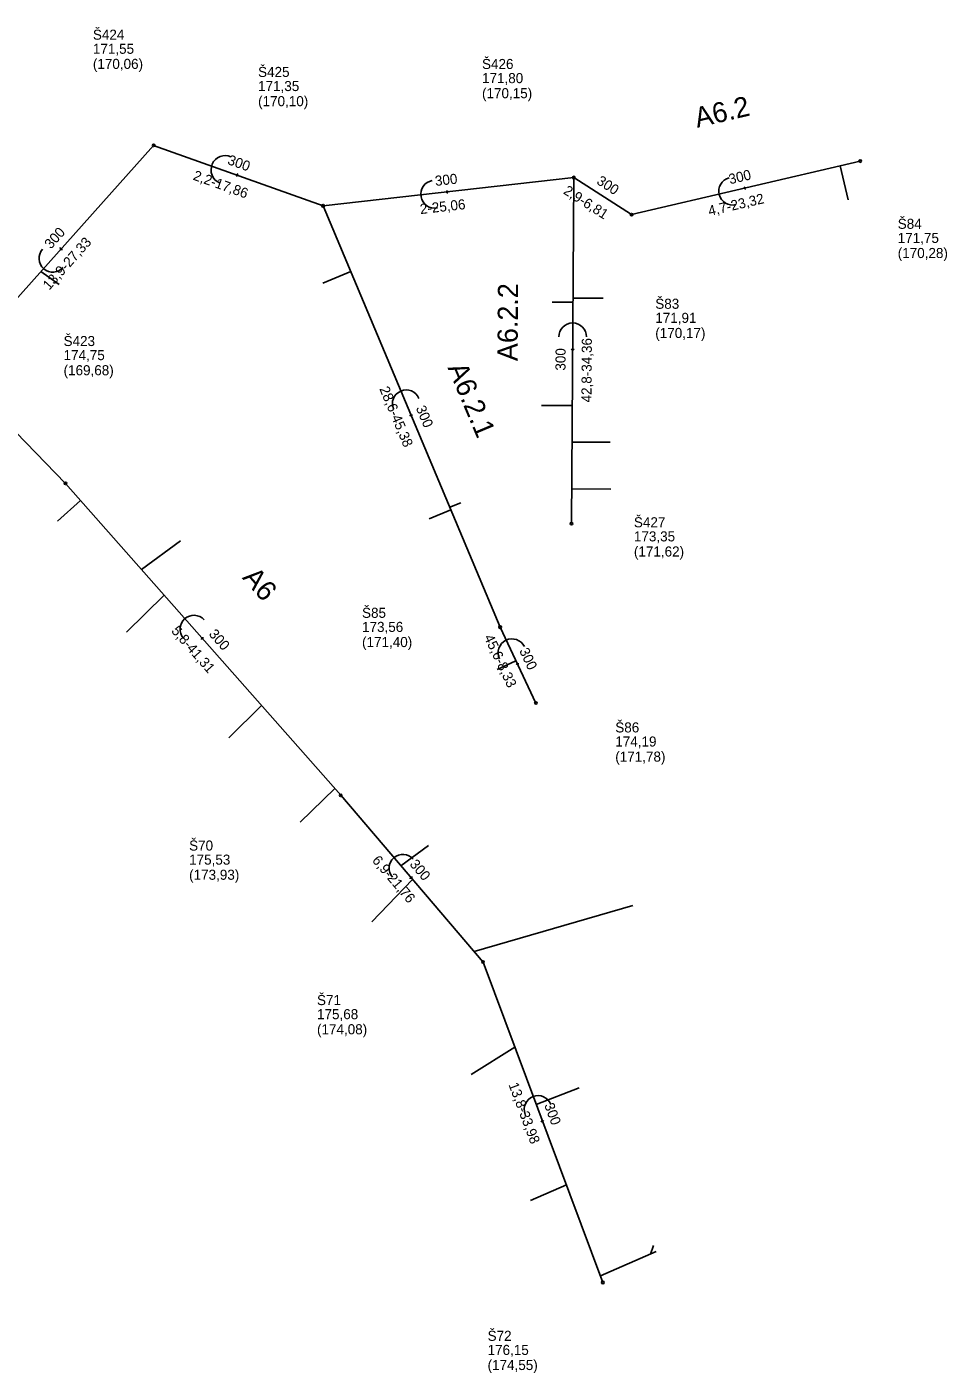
# Model space of a CAD drawing. Extents: x -548529 to -543591, y -1201432 to -1192608.
# Drawn here: x -546811.8 to -546720.5, y -1194923.8 to -1194790.1 of the extents above; entities that cross this region are included whole.
import ezdxf

# ---------------------------------------------------------------- set-up
doc = ezdxf.new("R2010")
doc.units = 0
for name, color, linetype in [('C3D_Bod-Značky', 7, 'Continuous'), ('C3D_Koridor', 7, 'Continuous'), ('C3D_Křižovatka', 7, 'Continuous'), ('C3D_Netisknutelná', 7, 'Continuous'), ('C3D_PP-zobrazeni v PR', 7, 'Continuous'), ('C3D_PR-Popisek', 7, 'Continuous'), ('C3D_SPR-Popisek', 7, 'Continuous'), ('C3D_Tlakove_potrubi_Popis', 7, 'Continuous'), ('C3D_ZPR-Formaty', 7, 'Continuous')]:
    doc.layers.add(name, color=color, linetype=linetype)

# ---------------------------------------------------------------- blocks, each defined once
blk = doc.blocks.new('100')
at = {"layer": 'Defpoints'}
blk.add_circle((0, 0), 0.127, dxfattribs=at)
blk = doc.blocks.new('86')
at = {"layer": 'Defpoints'}
blk.add_lwpolyline([(0.08, 0.14), (0.19, 0), (0.08, -0.14)], dxfattribs=at)
blk.add_arc((1.37, 0), 1.37, 270, 90, dxfattribs=at)
blk = doc.blocks.new('91')
at = {"layer": 'Defpoints'}
blk.add_lwpolyline([(0.08, 0.14), (0.19, 0), (0.08, -0.14)], dxfattribs=at)
blk.add_arc((1.37, 0), 1.37, 270, 90, dxfattribs=at)

msp = doc.modelspace()

# ---------------------------------------------------------------- linework, layer by layer
at = {"layer": 'C3D_Bod-Značky'}
for points in [[(-546799.24, -1194801.84), (-546817.46, -1194822.21)], [(-546782.42, -1194807.84), (-546799.24, -1194801.84)], [(-546729.09, -1194803.4), (-546751.79, -1194808.72)], [(-546757.52, -1194805.04), (-546782.42, -1194807.84)], [(-546757.76, -1194839.4), (-546757.52, -1194805.04)], [(-546751.79, -1194808.72), (-546757.52, -1194805.04)], [(-546764.84, -1194849.68), (-546782.42, -1194807.84)], [(-546807.989, -1194835.403), (-546818.831, -1194824.231)], [(-546780.666, -1194866.381), (-546807.989, -1194835.403)], [(-546761.29, -1194857.22), (-546764.84, -1194849.68)], [(-546766.539, -1194882.936), (-546780.666, -1194866.381)], [(-546754.646, -1194914.766), (-546766.539, -1194882.936)]]:
    msp.add_lwpolyline(points, dxfattribs=at)
at = {"layer": 'C3D_Koridor'}
for points in [[(-546731.091, -1194803.869), (-546730.283, -1194807.266)], [(-546810.431, -1194814.352), (-546808.618, -1194815.672)], [(-546779.677, -1194814.367), (-546782.443, -1194815.529)], [(-546757.604, -1194817.01), (-546754.604, -1194817.031)], [(-546757.606, -1194817.42), (-546759.689, -1194817.405)], [(-546757.678, -1194827.679), (-546760.741, -1194827.659)], [(-546757.704, -1194831.319), (-546753.918, -1194831.326)], [(-546757.736, -1194835.949), (-546753.862, -1194835.984)], [(-546806.493, -1194837.099), (-546808.777, -1194839.173)], [(-546769.734, -1194838.033), (-546771.874, -1194838.932)], [(-546769.838, -1194837.784), (-546768.754, -1194837.329)], [(-546800.447, -1194843.953), (-546796.562, -1194841.101)], [(-546798.186, -1194846.518), (-546801.925, -1194850.167)], [(-546763.269, -1194853.019), (-546765.131, -1194853.895)], [(-546788.53, -1194857.465), (-546791.79, -1194860.667)], [(-546781.261, -1194865.707), (-546784.704, -1194869.043)], [(-546774.694, -1194873.38), (-546771.946, -1194871.361)], [(-546773.538, -1194874.735), (-546777.588, -1194878.96)], [(-546767.421, -1194881.903), (-546751.662, -1194877.321)], [(-546763.379, -1194891.394), (-546767.73, -1194894.113)], [(-546761.251, -1194897.09), (-546757.01, -1194895.42)], [(-546758.269, -1194905.071), (-546761.839, -1194906.608)], [(-546754.891, -1194914.11), (-546749.361, -1194911.7)], [(-546749.906, -1194911.937), (-546749.629, -1194911.086)]]:
    msp.add_lwpolyline(points, dxfattribs=at)

# ---------------------------------------------------------------- block references
at = {"layer": 'C3D_PP-zobrazeni v PR'}
for p, xscale, yscale, rotation in [((-546799.24, -1194801.84), 0.999999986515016, 0.9999999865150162, 15.000000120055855), ((-546729.09, -1194803.4), 1.0009848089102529, 1.000984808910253, 14.224326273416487), ((-546757.52, -1194805.04), 1.0028916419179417, 1.0028916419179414, -13.69720873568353), ((-546782.42, -1194807.84), 1.0011217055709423, 1.0011217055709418, -6.582609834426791), ((-546751.79, -1194808.72), 1.008377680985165, 1.0083776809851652, -11.626378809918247), ((-546807.989, -1194835.403), 1.00000000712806, 1.00000000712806, 133.00000056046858), ((-546764.84, -1194849.68), 0.9999999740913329, 0.9999999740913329, -65.99999939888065), ((-546761.29, -1194857.22), 1.0000000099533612, 1.0000000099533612, -63.999999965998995), ((-546780.666, -1194866.381), 1.0000000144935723, 1.0000000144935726, 130.99999910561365), ((-546766.539, -1194882.936), 1.0000000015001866, 1.0000000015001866, 120.99999982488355), ((-546754.646, -1194914.766), 0.9999999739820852, 0.9999999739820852, -68.99999941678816)]:
    msp.add_blockref('100', p, dxfattribs=dict(at, xscale=xscale, yscale=yscale, rotation=rotation))
at = {"layer": 'C3D_PP-zobrazeni v PR', "rotation": -90}
msp.add_blockref('100', (-546757.76, -1194839.4), dxfattribs=at)
at = {"layer": 'C3D_SPR-Popisek'}
for name, p, xscale, yscale, rotation in [('86', (-546790.83, -1194804.84), 1.0316957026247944, 1.0316957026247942, 156.4154111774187), ('86', (-546769.97, -1194806.44), 1.0098116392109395, 1.0098116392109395, -169.38969821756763), ('86', (-546740.44, -1194806.06), 1.0009848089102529, 1.000984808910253, -165.77567372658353), ('86', (-546808.35, -1194812.025), 1.0000000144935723, 1.0000000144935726, -130.99999910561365), ('86', (-546773.63, -1194828.76), 1.0000000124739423, 1.000000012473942, 112.99999954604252), ('91', (-546794.327, -1194850.892), 1.0000000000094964, 1.0000000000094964, 132.0000013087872), ('86', (-546763.065, -1194853.45), 1.0000000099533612, 1.0000000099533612, 116.000000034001), ('91', (-546773.602, -1194874.658), 1.0000000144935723, 1.0000000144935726, 130.99999910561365), ('91', (-546760.592, -1194898.851), 0.9999999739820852, 0.9999999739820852, 111.00000058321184)]:
    msp.add_blockref(name, p, dxfattribs=dict(at, xscale=xscale, yscale=yscale, rotation=rotation))
at = {"layer": 'C3D_SPR-Popisek', "rotation": 90}
msp.add_blockref('86', (-546757.64, -1194822.22), dxfattribs=at)

# ---------------------------------------------------------------- texts
at = {"layer": 'C3D_Křižovatka'}
for s, p in [('Š424', (-546805.27, -1194791.35)), ('Š426', (-546766.64, -1194794.26)), ('Š425', (-546788.87, -1194795.05)), ('Š84', (-546725.37, -1194810.13)), ('Š83', (-546749.44, -1194818.07)), ('Š423', (-546808.18, -1194821.77)), ('Š427', (-546751.56, -1194839.77)), ('Š85', (-546778.55, -1194848.76)), ('Š86', (-546753.41, -1194860.14)), ('Š70', (-546795.716, -1194871.871)), ('Š71', (-546783.019, -1194887.216)), ('Š72', (-546766.086, -1194920.556))]:
    msp.add_text(s, height=1, dxfattribs=at).set_placement(p)
at = {"layer": 'C3D_Netisknutelná'}
for s, rotation, p in [('A6.2', 13.19, (-546745.28, -1194800.107)), ('A6.2.2', 89.6, (-546763.112, -1194823.268)), ('A6.2.1', 292.79, (-546770.079, -1194823.915)), ('A6', 311.41, (-546790.497, -1194844.808))]:
    msp.add_text(s, height=2, rotation=rotation, dxfattribs=at).set_placement(p)
at = {"layer": 'C3D_PR-Popisek'}
for rotation, p in [(340.37, (-546791.977, -1194803.688)), (6.42, (-546771.255, -1194805.876)), (327.29, (-546755.341, -1194805.608)), (13.19, (-546742.021, -1194805.709)), (48.19, (-546809.437, -1194812.196)), (89.6, (-546758.354, -1194824.214)), (292.79, (-546773.227, -1194827.92)), (311.41, (-546793.822, -1194850.413)), (295.21, (-546762.967, -1194852.021)), (310.48, (-546773.882, -1194873.258)), (290.49, (-546760.48, -1194897.141))]:
    msp.add_text('300', height=1, rotation=rotation, dxfattribs=at).set_placement(p)
at = {"layer": 'C3D_Tlakove_potrubi_Popis'}
for s, p in [('171,55 ', (-546805.27, -1194792.75)), ('(170,06)', (-546805.27, -1194794.25)), ('171,35 ', (-546788.87, -1194796.45)), ('171,80 ', (-546766.64, -1194795.66)), ('(170,10)', (-546788.87, -1194797.95)), ('(170,15)', (-546766.64, -1194797.16)), ('171,75 ', (-546725.37, -1194811.53)), ('(170,28)', (-546725.37, -1194813.03)), ('171,91 ', (-546749.44, -1194819.47)), ('(170,17)', (-546749.44, -1194820.97)), ('174,75 ', (-546808.18, -1194823.17)), ('(169,68)', (-546808.18, -1194824.67)), ('173,35 ', (-546751.56, -1194841.17)), ('(171,62)', (-546751.56, -1194842.67)), ('173,56 ', (-546778.55, -1194850.16)), ('(171,40)', (-546778.55, -1194851.66)), ('174,19 ', (-546753.41, -1194861.54)), ('(171,78)', (-546753.41, -1194863.04)), ('175,53 ', (-546795.716, -1194873.271)), ('(173,93)', (-546795.716, -1194874.771)), ('175,68 ', (-546783.019, -1194888.616)), ('(174,08)', (-546783.019, -1194890.116)), ('176,15 ', (-546766.086, -1194921.956)), ('(174,55)', (-546766.086, -1194923.456))]:
    msp.add_text(s, height=1, dxfattribs=at).set_placement(p)
at = {"layer": 'C3D_ZPR-Formaty'}
for s, rotation, p in [('2,2-17,86', 340.37, (-546795.401, -1194805.23)), ('2,9-6,81', 327.29, (-546758.641, -1194806.58)), ('2-25,06', 6.42, (-546772.747, -1194808.669)), ('4,7-23,32', 13.19, (-546744.06, -1194808.858)), ('13,9-27,33', 48.19, (-546809.604, -1194816.277)), ('42,8-34,36', 89.6, (-546755.776, -1194827.373)), ('28,6-45,38', 292.79, (-546776.847, -1194826.018)), ('5,8-41,31', 311.41, (-546797.548, -1194850.104)), ('45,6-8,33', 295.21, (-546766.464, -1194850.685)), ('6,9-21,76', 310.48, (-546777.61, -1194872.883)), ('13,8-33,98', 290.49, (-546764.024, -1194895.111))]:
    msp.add_text(s, height=1, rotation=rotation, dxfattribs=at).set_placement(p)

doc.saveas('drawing.dxf')
